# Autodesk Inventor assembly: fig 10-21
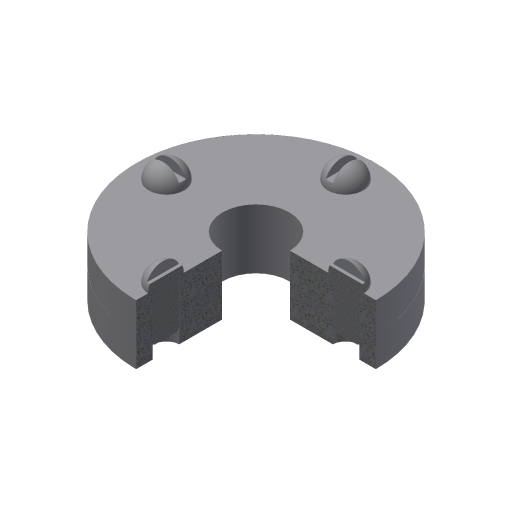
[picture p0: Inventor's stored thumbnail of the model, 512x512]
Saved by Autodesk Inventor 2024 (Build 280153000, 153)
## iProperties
Shininess: 64.0
Angle Display Precision: 2
Document Length Units: 11269
Document Angle Units: 11279
Document Time Units: 11290
Document Mass Units: 11283
Document Length Units Precision: 3
Document Angle Units Precision: 2
Created: 2002-02
Part Number: fig 10-21
Document SubType Name: Assembly
Designer: ***
Density: 0.0
Volumn: 0.0
Area: 0.0
PropertySet Name: Model Information
Control State: 0
Master: False
Checked Out: False
Author: ***
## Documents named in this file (3)
- D:\PROJECTS\Project 2023\RESOURCES INVENTOR 2024\RESOURCES INVENTOR 2024\Inventor_2023_Part\Inventor_2024_Part\c10_Inv_2024_prt\fig 10-21.iam
- D:\PROJECTS\Project 2023\RESOURCES INVENTOR 2024\RESOURCES INVENTOR 2024\Inventor_2023_Part\Inventor_2024_Part\c10_Inv_2024_prt\Screw.ipt
- D:\PROJECTS\Project 2023\RESOURCES INVENTOR 2024\RESOURCES INVENTOR 2024\Inventor_2023_Part\Inventor_2024_Part\c10_Inv_2024_prt\test.ipt
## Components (6 placed, 2 different names)
1. test:1 — Insert:1, Insert:2
2. test:2 — Insert:1
3. Screw:1 — Angle:1, Insert:2
4. Screw:11
5. Screw:12
6. Screw:13
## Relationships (3: Insert 2, Angle 1)
- Insert:1: test:1 ↔ test:2
- Angle:1: Screw:1
- Insert:2: test:1 ↔ Screw:1
